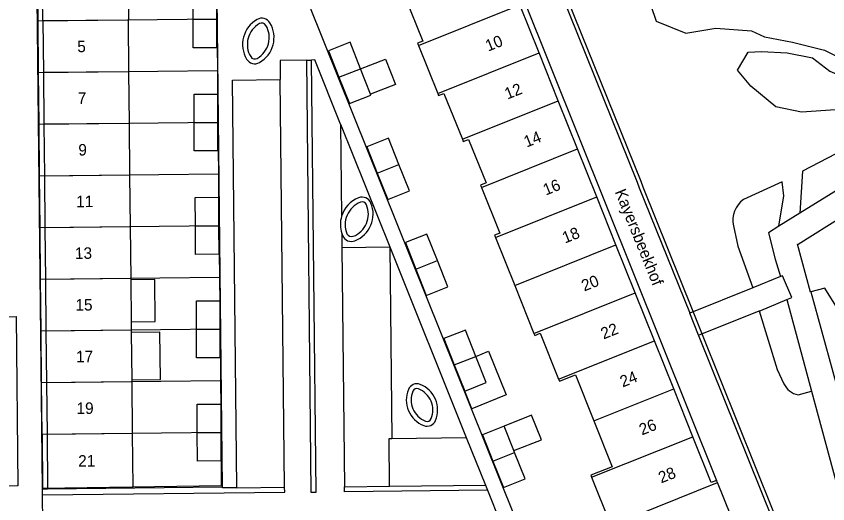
# Model space of a CAD drawing. Extents: x 194485 to 197793, y 468269 to 470822.
# Drawn here: x 194757.7 to 194842.4, y 469474.2 to 469525.2 of the extents above; entities that cross this region are included whole.
import ezdxf

# ---------------------------------------------------------------- set-up
doc = ezdxf.new("R2010")
doc.units = 0
for name, color, linetype in [('BGT grensvlak begroeid terreindeel', 7, 'Continuous'), ('BGT grensvlak gebouwinstallatie plus 1', 7, 'Continuous'), ('BGT grensvlak onbegroeid terreindeel', 7, 'Continuous'), ('BGT grensvlak overbruggingsdeel plus 1', 7, 'Continuous'), ('BGT grensvlak pand op maaiveld', 7, 'Continuous'), ('BGT grensvlak pand op maaiveld LR', 7, 'Continuous'), ('BGT grensvlak scheiding', 7, 'Continuous'), ('BGT grensvlak wegdeel', 7, 'Continuous'), ('BGT tekst huisnummerreeks', 7, 'Continuous'), ('BGT tekst openbare ruimte label terrein', 7, 'Continuous'), ('GEM grensvlak WOZ_BRK percelen', 7, 'Continuous')]:
    doc.layers.add(name, color=color, linetype=linetype)

msp = doc.modelspace()

# ---------------------------------------------------------------- linework, layer by layer
at = {"layer": 'BGT grensvlak begroeid terreindeel'}
msp.add_line((194839.32, 469485.63), (194840.734, 469485.995), dxfattribs=at)
for points in [[(194850.287, 469511.281), (194848.594, 469514.055), (194844.131, 469511.249), (194839.789, 469509), (194839.519, 469504.602)], [(194837.312, 469503.233), (194837.825, 469506.426), (194837.673, 469507.87), (194833.618, 469506.047)], [(194832.577, 469503.289), (194833.045, 469501.154), (194834.599, 469496.818)], [(194835.276, 469494.389), (194837.146, 469488.274), (194837.851, 469486.791)]]:
    msp.add_lwpolyline(points, dxfattribs=at)
for centre, radius, start, end in [((194835.275, 469503.846), 2.755, 126.97757, 191.66466), ((194839.715, 469487.639), 2.048, 204.47359, 258.88541)]:
    msp.add_arc(centre, radius, start, end, dxfattribs=at)
at = {"layer": 'BGT grensvlak gebouwinstallatie plus 1'}
for points in [[(194793.637, 469519.689), (194796.229, 469520.707), (194797.268, 469518.064), (194794.676, 469517.046)], [(194769.708, 469493.253), (194772.197, 469493.279), (194772.152, 469497.66), (194769.663, 469497.635)], [(194769.77, 469487.205), (194772.728, 469487.235), (194772.678, 469492.16), (194769.72, 469492.13)], [(194805.675, 469489.647), (194807.012, 469490.182), (194808.854, 469485.62), (194805.249, 469484.164), (194804.51, 469485.995)], [(194809.643, 469479.796), (194812.517, 469480.939), (194811.503, 469483.488), (194808.629, 469482.345)]]:
    msp.add_lwpolyline(points, dxfattribs=at)
at = {"layer": 'BGT grensvlak onbegroeid terreindeel'}
for points in [[(194823.934, 469526.311), (194824.506, 469524.67), (194827.611, 469523.408), (194830.753, 469523.941), (194834.471, 469523.641), (194835.824, 469523.024), (194838.744, 469522.475), (194842.098, 469521.629), (194845.833, 469519.761), (194850.583, 469520.527), (194853.695, 469520.537), (194859.356, 469521.82), (194861.044, 469523.795), (194865.497, 469526.077)], [(194843.684, 469518.975), (194843.246, 469515.407), (194839.693, 469515.142), (194836.992, 469515.716), (194834.381, 469517.89), (194832.991, 469519.554), (194834.103, 469521.425), (194835.501, 469521.496), (194838.195, 469521.356), (194840.841, 469520.82), (194842.637, 469519.455), (194843.684, 469518.975)]]:
    msp.add_lwpolyline(points, dxfattribs=at)
at = {"layer": 'BGT grensvlak overbruggingsdeel plus 1'}
for p, q in [((194837.484, 469497.981), (194834.599, 469496.818)), ((194834.599, 469496.818), (194828.029, 469494.171)), ((194828.942, 469491.855), (194835.276, 469494.389)), ((194828.942, 469491.855), (194828.029, 469494.171))]:
    msp.add_line(p, q, dxfattribs=at)
for points in [[(194838.139, 469495.572), (194838.673, 469495.793), (194837.708, 469498.071), (194837.484, 469497.981)], [(194835.276, 469494.389), (194835.426, 469494.449), (194838.139, 469495.572)]]:
    msp.add_lwpolyline(points, dxfattribs=at)
at = {"layer": 'BGT grensvlak pand op maaiveld'}
for p, q in [((194760.452, 469524.686), (194760.395, 469530.289)), ((194812.278, 469521.348), (194810.27, 469526.36)), ((194769.442, 469519.378), (194769.387, 469524.778)), ((194760.452, 469524.686), (194760.508, 469519.286)), ((194799.682, 469522.12), (194801.695, 469517.109)), ((194814.286, 469516.335), (194812.278, 469521.348)), ((194794.676, 469517.046), (194793.637, 469519.689)), ((194760.508, 469519.286), (194760.563, 469513.887)), ((194769.497, 469513.978), (194769.442, 469519.378)), ((194816.294, 469511.322), (194814.286, 469516.335)), ((194760.563, 469513.887), (194760.618, 469508.487)), ((194769.552, 469508.578), (194769.497, 469513.978)), ((194818.302, 469506.309), (194816.294, 469511.322)), ((194760.618, 469508.487), (194760.674, 469503.087)), ((194769.607, 469503.179), (194769.552, 469508.578)), ((194820.31, 469501.297), (194818.302, 469506.309)), ((194760.674, 469503.087), (194760.729, 469497.688)), ((194769.662, 469497.779), (194769.607, 469503.179)), ((194807.722, 469502.071), (194809.732, 469497.059)), ((194822.318, 469496.284), (194820.31, 469501.297)), ((194760.729, 469497.688), (194760.784, 469492.288)), ((194769.663, 469497.635), (194769.662, 469497.779)), ((194769.708, 469493.253), (194769.663, 469497.635)), ((194809.732, 469497.059), (194811.742, 469492.047)), ((194824.326, 469491.271), (194822.318, 469496.284)), ((194769.717, 469492.379), (194769.708, 469493.253)), ((194760.784, 469492.288), (194760.839, 469486.888)), ((194769.72, 469492.13), (194769.717, 469492.379)), ((194769.77, 469487.205), (194769.72, 469492.13)), ((194826.334, 469486.258), (194824.326, 469491.271)), ((194803.421, 469488.746), (194804.51, 469485.995)), ((194760.839, 469486.888), (194760.895, 469481.488)), ((194769.772, 469486.98), (194769.77, 469487.205)), ((194769.826, 469481.58), (194769.772, 469486.98)), ((194828.342, 469481.246), (194826.334, 469486.258)), ((194809.643, 469479.796), (194808.629, 469482.345)), ((194760.895, 469481.488), (194760.952, 469475.885)), ((194809.723, 469479.595), (194809.643, 469479.796)), ((194817.766, 469477.009), (194819.788, 469472.002)), ((194830.915, 469476.459), (194830.823, 469476.688))]:
    msp.add_line(p, q, dxfattribs=at)
for points in [[(194760.395, 469530.289), (194769.33, 469530.408), (194769.387, 469524.778)], [(194776.16, 469524.874), (194776.169, 469527.848), (194778.593, 469527.838), (194778.588, 469524.882)], [(194798.24, 469527.358), (194800.149, 469522.577), (194799.589, 469522.352), (194799.682, 469522.12)], [(194778.588, 469524.882), (194778.582, 469521.89), (194776.15, 469521.894), (194776.16, 469524.874)], [(194793.637, 469519.689), (194792.549, 469522.455), (194790.286, 469521.582), (194791.381, 469518.819)], [(194791.381, 469518.819), (194792.477, 469516.055), (194794.724, 469516.923), (194794.676, 469517.046)], [(194776.257, 469514.07), (194776.247, 469517.038), (194778.682, 469517.047), (194778.695, 469514.09)], [(194801.695, 469517.109), (194801.779, 469516.901), (194802.344, 469517.114), (194804.265, 469512.321)], [(194778.695, 469514.09), (194778.709, 469511.124), (194776.267, 469511.111), (194776.257, 469514.07)], [(194797.64, 469509.685), (194796.545, 469512.44), (194794.283, 469511.536), (194795.379, 469508.777)], [(194804.265, 469512.321), (194804.353, 469512.102), (194804.909, 469512.316), (194806.737, 469507.763), (194806.176, 469507.524), (194806.264, 469507.304)], [(194795.379, 469508.777), (194796.476, 469506.017), (194798.736, 469506.929), (194797.64, 469509.685)], [(194806.264, 469507.304), (194808.185, 469502.512), (194807.632, 469502.295), (194807.722, 469502.071)], [(194776.386, 469503.267), (194776.377, 469506.252), (194778.804, 469506.261), (194778.816, 469503.291)], [(194840.669, 469496.37), (194840.627, 469496.359), (194839.269, 469501.354), (194839.322, 469501.382), (194844.115, 469504.359)], [(194778.816, 469503.291), (194778.829, 469500.308), (194776.395, 469500.294), (194776.386, 469503.267)], [(194801.653, 469499.658), (194800.571, 469502.414), (194798.318, 469501.528), (194799.399, 469498.769)], [(194799.399, 469498.769), (194800.48, 469496.009), (194802.736, 469496.901), (194801.653, 469499.658)], [(194850.099, 469494.696), (194849.905, 469494.576), (194848.947, 469496.12), (194844.312, 469493.243), (194842.133, 469496.765), (194840.669, 469496.37)], [(194776.494, 469492.464), (194776.492, 469495.447), (194778.939, 469495.449), (194778.942, 469492.484)], [(194778.942, 469492.484), (194778.945, 469489.503), (194776.495, 469489.495), (194776.494, 469492.464)], [(194805.675, 469489.647), (194804.604, 469492.396), (194802.332, 469491.496), (194803.421, 469488.746)], [(194811.742, 469492.047), (194811.827, 469491.836), (194812.394, 469492.051), (194814.317, 469487.261)], [(194804.51, 469485.995), (194806.746, 469486.898), (194805.675, 469489.647)], [(194814.317, 469487.261), (194814.401, 469487.053), (194816.07, 469487.711), (194817.993, 469482.917)], [(194776.587, 469481.673), (194776.58, 469484.655), (194779.036, 469484.664), (194779.045, 469481.695)], [(194817.993, 469482.917), (194819.92, 469478.116), (194817.682, 469477.217), (194817.766, 469477.009)], [(194760.952, 469475.885), (194769.883, 469476.019), (194769.826, 469481.58)], [(194779.045, 469481.695), (194779.055, 469478.713), (194776.594, 469478.703), (194776.587, 469481.673)], [(194808.629, 469482.345), (194806.357, 469481.452), (194807.455, 469478.702)], [(194830.823, 469476.688), (194830.259, 469476.461), (194828.342, 469481.246)], [(194807.455, 469478.702), (194808.553, 469475.951), (194810.816, 469476.845), (194809.723, 469479.595)], [(194832.976, 469471.184), (194833.029, 469471.205), (194830.915, 469476.459)]]:
    msp.add_lwpolyline(points, dxfattribs=at)
at = {"layer": 'BGT grensvlak pand op maaiveld LR'}
for p, q in [((194799.682, 469522.12), (194810.27, 469526.36)), ((194769.387, 469524.778), (194760.452, 469524.686)), ((194776.16, 469524.874), (194778.588, 469524.882)), ((194801.695, 469517.109), (194812.278, 469521.348)), ((194791.381, 469518.819), (194793.637, 469519.689)), ((194769.442, 469519.378), (194760.508, 469519.286)), ((194804.265, 469512.321), (194814.286, 469516.335)), ((194769.497, 469513.978), (194760.563, 469513.887)), ((194776.257, 469514.07), (194778.695, 469514.09)), ((194806.264, 469507.304), (194816.294, 469511.322)), ((194795.379, 469508.777), (194797.64, 469509.685)), ((194769.552, 469508.578), (194760.618, 469508.487)), ((194807.722, 469502.071), (194818.302, 469506.309)), ((194769.607, 469503.179), (194760.674, 469503.087)), ((194776.386, 469503.267), (194778.816, 469503.291)), ((194809.732, 469497.059), (194820.31, 469501.297)), ((194799.399, 469498.769), (194801.653, 469499.658)), ((194769.662, 469497.779), (194760.729, 469497.688)), ((194811.742, 469492.047), (194822.318, 469496.284)), ((194769.717, 469492.379), (194760.784, 469492.288)), ((194776.494, 469492.464), (194778.942, 469492.484)), ((194814.317, 469487.261), (194824.326, 469491.271)), ((194803.421, 469488.746), (194805.675, 469489.647)), ((194769.772, 469486.98), (194760.839, 469486.888)), ((194817.993, 469482.917), (194826.334, 469486.258)), ((194769.826, 469481.58), (194760.895, 469481.488)), ((194776.587, 469481.673), (194779.045, 469481.695)), ((194817.766, 469477.009), (194828.342, 469481.246)), ((194807.455, 469478.702), (194809.723, 469479.595)), ((194819.788, 469472.002), (194830.915, 469476.459))]:
    msp.add_line(p, q, dxfattribs=at)
at = {"layer": 'BGT grensvlak scheiding'}
for points in [[(194808.402, 469544.028), (194813.167, 469532.11), (194822.891, 469507.949), (194823.111, 469507.354), (194828.346, 469494.356), (194829.297, 469491.931), (194842.241, 469459.762), (194843.193, 469457.323), (194846.06, 469450.233), (194846.279, 469449.635), (194849.21, 469442.337)], [(194828.029, 469494.171), (194828.009, 469494.221), (194822.775, 469507.204), (194822.548, 469507.812), (194812.834, 469531.96), (194812.809, 469532.023)], [(194841.914, 469459.568), (194828.963, 469491.802), (194828.942, 469491.855)]]:
    msp.add_lwpolyline(points, dxfattribs=at)
for centre, radius, start, end in [((194784.307, 469522.235), 2.999, 119.66166, 210.75312), ((194783.318, 469523.973), 0.999, 30.75793, 119.7008), ((194784.307, 469522.235), 2.499, 119.64773, 210.76871), ((194781.598, 469522.951), 2.501, 299.67547, 30.70992), ((194783.318, 469523.971), 0.501, 30.89292, 119.48668), ((194781.598, 469522.95), 3, 299.68013, 30.74148), ((194782.588, 469521.209), 0.997, 210.55826, 299.82134), ((194782.591, 469521.217), 0.503, 211.1247, 299.21302), ((194794.528, 469503.416), 3.002, 111.50333, 163.31743), ((194793.794, 469505.278), 1, 22.49235, 111.47548), ((194794.529, 469503.416), 2.502, 111.51642, 202.50794), ((194791.947, 469504.512), 2.5, 291.45351, 22.52875), ((194791.947, 469504.512), 3, 291.47688, 22.51955), ((194793.794, 469505.278), 0.501, 22.56602, 111.40181), ((194794.526, 469503.417), 2.999, 163.31926, 197.96391), ((194794.316, 469503.332), 2.773, 197.64134, 202.57113), ((194792.677, 469502.646), 0.996, 202.2897, 291.67813), ((194792.681, 469502.656), 0.504, 203.08819, 290.96637), ((194799.51, 469485.823), 0.957, 68.6629, 157.70063), ((194798.815, 469484.039), 2.871, 337.61903, 68.70473), ((194801.281, 469485.094), 2.872, 157.65597, 248.67879), ((194801.28, 469485.093), 2.37, 157.61864, 248.70739), ((194799.51, 469485.823), 0.457, 68.72243, 157.67475), ((194798.816, 469484.039), 2.371, 337.63516, 68.722), ((194800.585, 469483.311), 0.957, 248.67908, 337.60589), ((194800.585, 469483.311), 0.457, 248.68434, 337.64238)]:
    msp.add_arc(centre, radius, start, end, dxfattribs=at)
at = {"layer": 'BGT grensvlak wegdeel'}
for p, q in [((194806.899, 469536.384), (194830.823, 469476.688)), ((194779.213, 469476.004), (194778.63, 469530.527)), ((194788.002, 469520.6), (194788.527, 469520.606)), ((194780.259, 469518.517), (194785.251, 469518.571)), ((194780.714, 469475.922), (194780.259, 469518.517)), ((194785.708, 469475.977), (194785.251, 469518.571)), ((194791.546, 469513.899), (194791.653, 469504.278)), ((194791.546, 469513.899), (194796.691, 469501.072)), ((194850.287, 469511.281), (194839.519, 469504.602)), ((194839.519, 469504.602), (194837.312, 469503.233)), ((194791.673, 469502.492), (194791.689, 469501.02)), ((194791.689, 469501.02), (194796.691, 469501.072)), ((194796.691, 469501.072), (194804.68, 469481.156)), ((194796.691, 469501.072), (194796.906, 469481.073)), ((194791.689, 469501.02), (194791.964, 469476.021)), ((194840.669, 469496.37), (194843.33, 469486.63)), ((194838.139, 469495.572), (194840.734, 469485.995)), ((194796.906, 469481.073), (194804.68, 469481.156)), ((194804.68, 469481.156), (194806.677, 469476.177)), ((194760.412, 469475.803), (194760.953, 469475.809)), ((194760.418, 469475.164), (194760.412, 469475.803)), ((194760.953, 469475.809), (194779.213, 469476.004)), ((194780.714, 469475.922), (194785.708, 469475.977)), ((194791.964, 469476.021), (194796.66, 469476.071)), ((194796.66, 469476.071), (194806.677, 469476.177)), ((194806.677, 469476.177), (194806.887, 469475.654)), ((194806.887, 469475.654), (194809.185, 469469.924)), ((194760.477, 469469.736), (194760.418, 469475.164))]:
    msp.add_line(p, q, dxfattribs=at)
for points in [[(194785.176, 469534.079), (194812.726, 469465.392), (194812.726, 469465.362)], [(194760.412, 469475.803), (194759.829, 469530.281), (194760.353, 469530.288)], [(194788.002, 469520.6), (194785.229, 469520.57), (194785.251, 469518.571)], [(194788.002, 469520.6), (194788.456, 469475.452), (194788.981, 469475.457), (194788.527, 469520.606)], [(194791.546, 469513.899), (194788.855, 469520.61), (194788.527, 469520.606)], [(194837.312, 469503.233), (194836.221, 469502.556), (194836.929, 469499.815), (194837.484, 469497.981)], [(194755.688, 469493.791), (194757.665, 469493.803), (194757.85, 469476.102), (194755.863, 469476.069)], [(194840.734, 469485.995), (194843.279, 469476.606), (194847.282, 469461.733)], [(194796.66, 469476.071), (194796.606, 469481.07), (194796.906, 469481.073)], [(194760.418, 469475.164), (194785.714, 469475.454), (194785.708, 469475.977)], [(194780.714, 469475.922), (194779.214, 469475.906), (194779.213, 469476.004)], [(194806.887, 469475.654), (194791.97, 469475.484), (194791.964, 469476.021)]]:
    msp.add_lwpolyline(points, dxfattribs=at)
at = {"layer": 'GEM grensvlak WOZ_BRK percelen'}
for p, q in [((194759.957, 469524.681), (194759.898, 469530.778)), ((194778.568, 469530.967), (194778.629, 469524.873)), ((194778.629, 469524.873), (194759.957, 469524.681)), ((194778.629, 469524.873), (194778.684, 469519.473)), ((194760.01, 469519.281), (194759.957, 469524.681)), ((194778.684, 469519.473), (194760.01, 469519.281)), ((194760.063, 469513.882), (194760.01, 469519.281)), ((194778.684, 469519.473), (194778.738, 469514.072)), ((194778.738, 469514.072), (194760.063, 469513.882)), ((194760.115, 469508.482), (194760.063, 469513.882)), ((194778.738, 469514.072), (194778.793, 469508.672)), ((194778.793, 469508.672), (194760.115, 469508.482)), ((194778.793, 469508.672), (194778.847, 469503.274)), ((194760.168, 469503.082), (194760.115, 469508.482)), ((194778.847, 469503.274), (194760.168, 469503.082)), ((194760.221, 469497.683), (194760.168, 469503.082)), ((194778.847, 469503.274), (194778.902, 469497.873)), ((194778.902, 469497.873), (194760.221, 469497.683)), ((194760.273, 469492.283), (194760.221, 469497.683)), ((194778.902, 469497.873), (194778.956, 469492.473)), ((194778.956, 469492.473), (194760.273, 469492.283)), ((194760.326, 469486.883), (194760.273, 469492.283)), ((194778.956, 469492.473), (194779.011, 469487.075)), ((194779.011, 469487.075), (194760.326, 469486.883)), ((194760.378, 469481.483), (194760.326, 469486.883)), ((194779.011, 469487.075), (194779.065, 469481.675)), ((194779.065, 469481.675), (194760.378, 469481.483))]:
    msp.add_line(p, q, dxfattribs=at)
msp.add_lwpolyline([(194760.378, 469481.483), (194760.433, 469475.877), (194779.121, 469476.158), (194779.065, 469481.675)], dxfattribs=at)

# ---------------------------------------------------------------- texts
at = {"layer": 'BGT tekst huisnummerreeks'}
for s, rotation, p in [('10', 21.8, (194806.956, 469521.478)), ('5', 0.6, (194764.054, 469521.423)), ('12', 21.8, (194808.968, 469516.467)), ('7', 0.6, (194764.113, 469516.023)), ('14', 21.8, (194810.972, 469511.453)), ('9', 0.6, (194764.167, 469510.624)), ('16', 21.8, (194812.978, 469506.439)), ('11', 0.6, (194763.937, 469505.221)), ('18', 21.8, (194814.985, 469501.426)), ('13', 0.6, (194763.813, 469499.819)), ('20', 21.8, (194816.996, 469496.415)), ('15', 0.6, (194763.864, 469494.42)), ('22', 21.8, (194819.008, 469491.403)), ('17', 0.6, (194763.923, 469489.02)), ('24', 21.8, (194821.012, 469486.389)), ('19', 0.6, (194763.978, 469483.62)), ('26', 21.8, (194823.018, 469481.375)), ('21', 0.6, (194764.151, 469478.119)), ('28', 21.8, (194825.025, 469476.363))]:
    msp.add_text(s, height=1.2, rotation=rotation, dxfattribs=at).set_placement(p)
at = {"layer": 'BGT tekst openbare ruimte label terrein'}
msp.add_text('Kayersbeekhof', height=1.2, rotation=292, dxfattribs=at).set_placement((194820.171, 469506.841))

doc.saveas('drawing.dxf')
